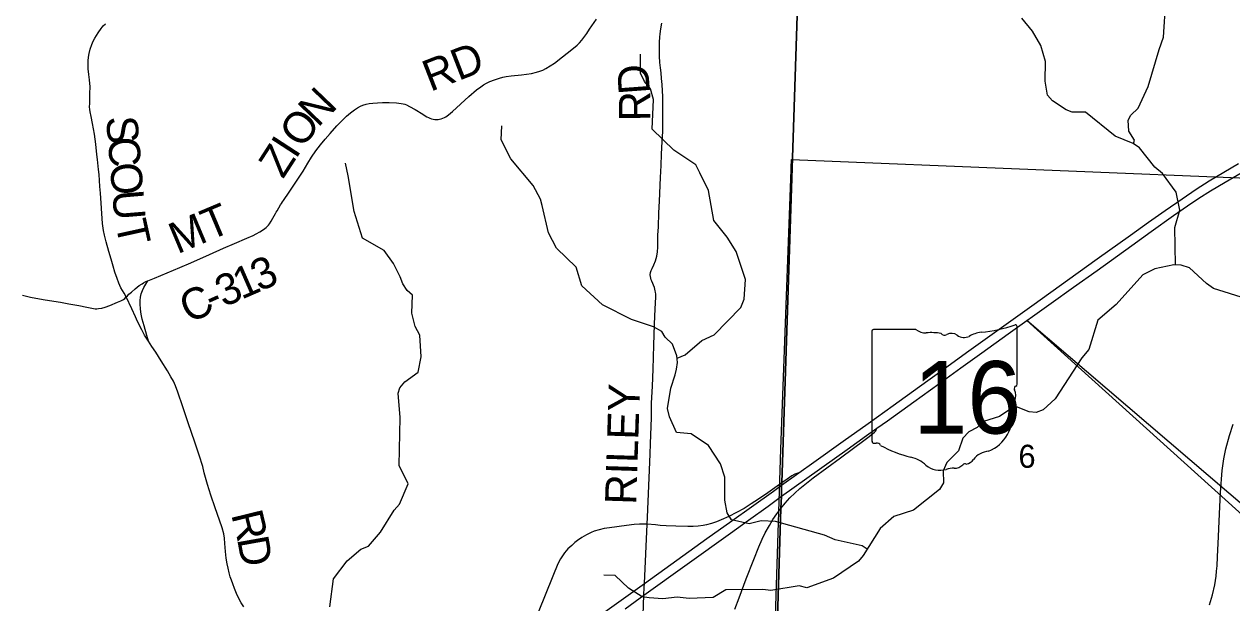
# Model space of a CAD drawing. Extents: x 0 to 34, y 0 to 22.
# Drawn here: x 4.796 to 6.991, y 19.468 to 20.52 of the extents above; entities that cross this region are included whole.
import ezdxf

# ---------------------------------------------------------------- set-up
doc = ezdxf.new("R2010")
doc.units = 0
for name, color, linetype in [('GM_X_County_Road', 7, 'Continuous'), ('GM_X_County_Road_Text', 7, 'Continuous'), ('GM_X_Interchange_Ramps', 7, 'Continuous'), ('GM_X_Minor_River', 7, 'Continuous'), ('GM_X_Section', 7, 'Continuous'), ('GM_X_Section_Text', 7, 'Continuous'), ('GM_X_State_Location', 7, 'Continuous'), ('GM_X_State_Route', 7, 'Continuous'), ('GM_X_State_Shield', 7, 'Continuous'), ('GM_X_Township', 7, 'Continuous'), ('GM_X_Township_Road', 7, 'Continuous'), ('GM_X_Township_Road_Text', 7, 'Continuous'), ('SH_Data', 7, 'Continuous')]:
    doc.layers.add(name, color=color, linetype=linetype)

msp = doc.modelspace()

# ---------------------------------------------------------------- linework, layer by layer
at = {"layer": 'GM_X_County_Road'}
for points in [[(5.021, 20.0533), (5.0333, 20.0583), (5.0791, 20.0773), (5.099, 20.086), (5.1329, 20.1014), (5.1585, 20.1128), (5.1785, 20.1211), (5.2011, 20.1308), (5.2125, 20.1358), (5.218, 20.1386), (5.2249, 20.1423), (5.2313, 20.1466), (5.2359, 20.1502), (5.2382, 20.1522), (5.2402, 20.1544), (5.2421, 20.1568), (5.2453, 20.162), (5.2484, 20.1673), (5.2529, 20.1754), (5.2545, 20.1781), (5.256, 20.1808), (5.2591, 20.1862), (5.2624, 20.1915), (5.2641, 20.194), (5.2658, 20.1966), (5.2676, 20.1991), (5.2781, 20.2145), (5.2915, 20.2344), (5.3031, 20.2528), (5.312, 20.2673), (5.3187, 20.2778), (5.3265, 20.2897), (5.3347, 20.3006), (5.3433, 20.3111), (5.3522, 20.3214), (5.3647, 20.335), (5.3753, 20.3461), (5.3821, 20.3526), (5.3892, 20.3587), (5.3967, 20.3644), (5.4019, 20.3679), (5.4077, 20.3706), (5.4118, 20.3724), (5.4176, 20.3744), (5.4231, 20.3756), (5.4299, 20.3763), (5.4382, 20.3769), (5.4476, 20.3772), (5.4595, 20.3772), (5.4731, 20.3768), (5.4818, 20.3757), (5.4849, 20.375), (5.488, 20.3742), (5.491, 20.3731), (5.4966, 20.3703), (5.5072, 20.3645), (5.5098, 20.363), (5.5177, 20.358), (5.5283, 20.3516), (5.531, 20.3502), (5.5338, 20.3489), (5.5367, 20.3479), (5.5396, 20.3471), (5.5425, 20.3465), (5.5455, 20.3464), (5.5485, 20.3465), (5.5514, 20.347), (5.5544, 20.3477), (5.5572, 20.3487), (5.56, 20.35), (5.5626, 20.3515), (5.5676, 20.355), (5.5747, 20.3609), (5.6046, 20.3881), (5.6187, 20.4003), (5.6261, 20.406), (5.6313, 20.4096), (5.6368, 20.4127), (5.6424, 20.4154), (5.6511, 20.4189), (5.66, 20.4218), (5.6661, 20.4234), (5.6723, 20.4245), (5.6815, 20.4258), (5.7001, 20.4276), (5.7093, 20.4287), (5.7185, 20.4302), (5.7275, 20.4324), (5.7333, 20.4342), (5.7391, 20.4365), (5.7446, 20.4392), (5.7525, 20.4439), (5.7601, 20.4492), (5.7748, 20.4605), (5.7919, 20.474), (5.8014, 20.4819), (5.8059, 20.4861), (5.8101, 20.4906), (5.8138, 20.4954), (5.8189, 20.5032), (5.8239, 20.511), (5.8367, 20.5287)], [(4.9817, 20.0239), (4.9778, 20.0308), (4.9722, 20.0407), (4.9684, 20.049), (4.9651, 20.0573), (4.9613, 20.0688), (4.958, 20.0798), (4.9544, 20.0925), (4.9504, 20.1069), (4.9451, 20.1242), (4.942, 20.1362), (4.9402, 20.145), (4.9387, 20.1573), (4.9373, 20.1758), (4.9361, 20.1944), (4.9349, 20.2129), (4.934, 20.225), (4.9324, 20.2463), (4.9315, 20.2555), (4.9294, 20.274), (4.9284, 20.2832), (4.9265, 20.3017), (4.9242, 20.3202), (4.9206, 20.3396), (4.9181, 20.3518), (4.9164, 20.3604), (4.9156, 20.3648), (4.9153, 20.3697), (4.9156, 20.3756), (4.9156, 20.3838), (4.9159, 20.3941), (4.9162, 20.4061), (4.9151, 20.4185), (4.9136, 20.4286), (4.9125, 20.4386), (4.9125, 20.4479), (4.9128, 20.4535), (4.9134, 20.4599), (4.9147, 20.4663), (4.9164, 20.4743), (4.9192, 20.4828), (4.9217, 20.4892), (4.9245, 20.4947), (4.9275, 20.4994), (4.9309, 20.5042), (4.9363, 20.5118), (4.94, 20.5166), (4.944, 20.5207)], [(4.9817, 20.0239), (4.9839, 20.0263), (4.9863, 20.0289), (4.9912, 20.0326), (4.9982, 20.0386), (5.0054, 20.0445), (5.0105, 20.0481), (5.0132, 20.0497), (5.0172, 20.0518), (5.021, 20.0533)], [(5.0222, 19.9435), (5.0192, 19.954), (5.0141, 19.9716), (5.0109, 19.9836), (5.009, 19.9927), (5.0076, 20.0019), (5.007, 20.0113), (5.0071, 20.0175), (5.0078, 20.0237), (5.0091, 20.0298), (5.01, 20.0328), (5.0111, 20.0357), (5.0138, 20.0413), (5.0154, 20.044), (5.021, 20.0533)], [(5.0222, 19.9435), (5.0152, 19.9545), (5.0099, 19.9642), (5.0025, 19.9796), (4.9985, 19.9881), (4.9919, 20.0024), (4.9817, 20.0239)], [(5.1956, 19.4608), (5.1907, 19.4682), (5.1864, 19.4758), (5.1821, 19.4846), (5.1786, 19.4938), (5.1754, 19.5023), (5.1731, 19.5089), (5.1708, 19.5154), (5.1686, 19.5224), (5.1668, 19.5307), (5.1653, 19.5388), (5.1637, 19.5489), (5.1625, 19.5613), (5.1613, 19.5756), (5.1605, 19.5854), (5.159, 19.5935), (5.1562, 19.6041), (5.1516, 19.618), (5.1437, 19.6406), (5.1358, 19.6634), (5.1294, 19.6833), (5.1237, 19.7045), (5.1209, 19.7156), (5.1145, 19.7364), (5.1067, 19.7599), (5.0946, 19.7951), (5.0846, 19.8244), (5.0756, 19.8507), (5.0712, 19.8623), (5.0674, 19.8708), (5.063, 19.8789), (5.0567, 19.8896), (5.0453, 19.908), (5.0353, 19.9237), (5.0284, 19.934), (5.0222, 19.9435)], [(6.9507, 19.4645), (6.9561, 19.4824), (6.9603, 19.5006), (6.9627, 19.5161), (6.9637, 19.5255), (6.9645, 19.5352), (6.9653, 19.5514), (6.9669, 19.5883), (6.9683, 19.6163), (6.9705, 19.6682), (6.974, 19.7084), (6.9769, 19.7299), (6.9806, 19.7481), (6.9871, 19.7721), (6.9939, 19.7927)]]:
    msp.add_lwpolyline(points, dxfattribs=at)
at = {"layer": 'GM_X_Interchange_Ramps'}
for points in [[(6.0878, 19.4563), (6.0956, 19.4767), (6.1087, 19.5117), (6.1223, 19.5466), (6.1316, 19.5697), (6.1379, 19.5839), (6.1433, 19.5952), (6.1508, 19.6088), (6.1573, 19.6194), (6.1643, 19.6297), (6.1717, 19.6397), (6.1797, 19.6493), (6.188, 19.6585), (6.1968, 19.6673), (6.206, 19.6756), (6.218, 19.6856), (6.2303, 19.6951), (6.2799, 19.7317), (6.3252, 19.7651), (6.3323, 19.7702), (6.3418, 19.7781), (6.344, 19.7807), (6.3464, 19.7852)], [(6.2041, 19.7041), (6.1972, 19.702), (6.1917, 19.699), (6.1829, 19.6926), (6.1733, 19.6859), (6.1479, 19.668), (6.131, 19.6561), (6.118, 19.6476), (6.1047, 19.6395), (6.0911, 19.632), (6.0772, 19.625), (6.0631, 19.6185), (6.0544, 19.615), (6.0456, 19.612), (6.0366, 19.6096), (6.0305, 19.6084), (6.0213, 19.6071), (6.012, 19.6065), (6.0027, 19.6064), (5.981, 19.6073), (5.9629, 19.608), (5.9524, 19.6086), (5.944, 19.6096), (5.9286, 19.6111)], [(5.9286, 19.6111), (5.9193, 19.6112), (5.9148, 19.6111), (5.9053, 19.6103), (5.8909, 19.6086), (5.8599, 19.6044), (5.8506, 19.6028), (5.8414, 19.6007), (5.8324, 19.5979), (5.8266, 19.5956), (5.8181, 19.5915), (5.8099, 19.5867), (5.8022, 19.5813), (5.7974, 19.5774), (5.7915, 19.5724), (5.7846, 19.5658), (5.7783, 19.5589), (5.7709, 19.5482), (5.7662, 19.5391), (5.7574, 19.5166), (5.7176, 19.4189)]]:
    msp.add_lwpolyline(points, dxfattribs=at)
at = {"layer": 'GM_X_Minor_River'}
for points in [[(6.8124, 20.3022), (6.8144, 20.3091), (6.8041, 20.3254), (6.8029, 20.3451), (6.8078, 20.3547), (6.8213, 20.3672), (6.8394, 20.4064), (6.8595, 20.474), (6.8674, 20.4964), (6.8716, 20.5616), (6.8769, 20.5715), (6.9002, 20.594), (6.9175, 20.6195), (6.9194, 20.6316), (6.9151, 20.6547), (6.9132, 20.6673), (6.8853, 20.7275), (6.8693, 20.7532), (6.8317, 20.8506)], [(6.889, 20.0821), (6.8878, 20.1504), (6.8967, 20.1816), (6.8901, 20.2142), (6.8654, 20.2486), (6.8517, 20.26), (6.8236, 20.2948), (6.8118, 20.3027), (6.7796, 20.3162), (6.7256, 20.3597), (6.7014, 20.3596), (6.69, 20.3641), (6.6653, 20.3803), (6.6562, 20.3906), (6.6519, 20.416), (6.6529, 20.452), (6.6445, 20.4808), (6.6288, 20.5073), (6.6094, 20.5308)], [(5.983, 19.9125), (5.9977, 19.9186), (6.0278, 19.9449), (6.0505, 19.9552), (6.0991, 20.0051), (6.1047, 20.0199), (6.1076, 20.0556), (6.0904, 20.1067), (6.0743, 20.1329), (6.05, 20.1631), (6.0403, 20.2173), (6.0246, 20.2495), (6.0174, 20.2643), (5.9771, 20.2911), (5.9376, 20.3289), (5.9404, 20.3828), (5.9346, 20.4025), (5.924, 20.4158), (5.9167, 20.4305), (5.9166, 20.4654)], [(6.3285, 19.5653), (6.3194, 19.5714), (6.2702, 19.5823), (6.2512, 19.5909), (6.1618, 19.6157), (6.1356, 19.6167), (6.1141, 19.6113), (6.0819, 19.6188), (6.0739, 19.6317), (6.07, 19.6548), (6.0698, 19.6965), (6.0621, 19.7208), (6.0404, 19.7541), (6.0085, 19.7752), (5.982, 19.7778), (5.969, 19.8058), (5.9655, 19.8214), (5.9714, 19.8582), (5.9793, 19.8825), (5.9819, 19.8924), (5.9837, 19.9049), (5.9825, 19.9167), (5.9745, 19.9379), (5.9616, 19.9507), (5.9555, 19.9614), (5.9403, 19.9696), (5.9001, 19.9828), (5.8477, 20.0095), (5.8097, 20.0443), (5.7998, 20.0781), (5.764, 20.1125), (5.7495, 20.1405), (5.7379, 20.1905), (5.7349, 20.2019), (5.7215, 20.2265), (5.6808, 20.2749), (5.6632, 20.3094), (5.6643, 20.3352)], [(5.3517, 19.4604), (5.3585, 19.5113), (5.3834, 19.5444), (5.4083, 19.5657), (5.4219, 19.5707), (5.4441, 19.5962), (5.4685, 19.6361), (5.4787, 19.6471), (5.4944, 19.684), (5.4776, 19.7177), (5.4795, 19.8049), (5.4763, 19.8489), (5.4789, 19.8588), (5.488, 19.8698), (5.5125, 19.887), (5.5181, 19.9151), (5.5152, 19.9545), (5.5072, 19.9705), (5.5011, 19.9947), (5.502, 20.0273), (5.4922, 20.0357), (5.4845, 20.0478), (5.4799, 20.0603), (5.4673, 20.0849), (5.4506, 20.1084), (5.4111, 20.131), (5.3958, 20.1791), (5.3849, 20.2443), (5.3806, 20.2671)], [(7.0178, 20.0208), (6.9583, 20.0391), (6.9454, 20.0482), (6.9142, 20.0769), (6.8991, 20.0818), (6.8862, 20.0821), (6.8514, 20.0752), (6.8295, 20.0641), (6.7813, 20.0101), (6.7481, 19.9815), (6.7313, 19.9283), (6.7188, 19.9135), (6.6703, 19.8386), (6.6485, 19.8188), (6.636, 19.8142), (6.6231, 19.8153), (6.5969, 19.8254), (6.569, 19.8064), (6.5399, 19.7975), (6.5286, 19.7869), (6.5135, 19.7789), (6.5022, 19.7671), (6.4947, 19.7443), (6.4736, 19.7233), (6.4665, 19.7078), (6.4673, 19.6861), (6.4602, 19.674), (6.413, 19.6366), (6.3771, 19.6251), (6.3522, 19.603), (6.3214, 19.554), (6.3127, 19.5437), (6.2674, 19.5125), (6.2191, 19.4952), (6.205, 19.499), (6.1532, 19.4904), (6.1388, 19.4923), (6.0718, 19.4917), (6.0488, 19.4776), (6.0049, 19.4755), (5.9833, 19.4785), (5.9572, 19.4754), (5.9322, 19.4768), (5.9197, 19.4786), (5.895, 19.4945), (5.8707, 19.5176), (5.8499, 19.5182)]]:
    msp.add_lwpolyline(points, dxfattribs=at)
at = {"layer": 'GM_X_Section'}
msp.add_lwpolyline([(6.1908, 20.2736), (7.0795, 20.2374), (7.0553, 19.2199), (6.1559, 19.253), (6.1718, 19.7471), (6.1903, 20.2549), (6.1905, 20.2588)], close=True, dxfattribs=at)
at = {"layer": 'GM_X_State_Route'}
for points in [[(5.5782, 19.2562), (5.9237, 19.5033), (5.9716, 19.5375), (6.0372, 19.5846), (6.0827, 19.6171), (6.1181, 19.6423), (6.1585, 19.6712), (6.1731, 19.6818), (6.2041, 19.7041), (6.2316, 19.7239), (6.2847, 19.7617), (6.3302, 19.7942), (6.3757, 19.8266), (6.4237, 19.861), (6.4666, 19.8918), (6.5094, 19.9227), (6.628, 20.0077), (6.7465, 20.093), (6.8072, 20.1362), (6.8399, 20.1598), (6.8703, 20.1814), (6.901, 20.2026), (6.9268, 20.2198), (6.9503, 20.2348), (6.9768, 20.2509), (7.0037, 20.2664)], [(5.8885, 19.4569), (5.9162, 19.4769), (5.9228, 19.4816), (6.0801, 19.5948), (6.1129, 19.6184), (6.1483, 19.6436), (6.1731, 19.6616), (6.1961, 19.6782), (6.2921, 19.7467), (6.3275, 19.7719), (6.3464, 19.7852), (6.3656, 19.7988), (6.4134, 19.8333), (6.4587, 19.8661), (6.4991, 19.895), (6.537, 19.9222), (6.5848, 19.9567), (6.6632, 20.0126), (6.7035, 20.0417), (6.7465, 20.0722), (6.8095, 20.1176), (6.8449, 20.1429), (6.8854, 20.1718), (6.9108, 20.1896), (6.9314, 20.2035), (6.9524, 20.2168), (6.979, 20.2329), (7.0086, 20.2499)]]:
    msp.add_lwpolyline(points, dxfattribs=at)
at = {"layer": 'GM_X_State_Shield'}
for p, q in [((6.3373, 19.9616), (6.3373, 19.7615)), ((6.4171, 19.9651), (6.3399, 19.9651)), ((6.601, 19.8653), (6.601, 19.97)), ((6.601, 19.8654), (6.601, 19.8653))]:
    msp.add_line(p, q, dxfattribs=at)
for centre, radius, start, end in [((6.3403, 19.962), 0.00305, 98.1301, 188.1301), ((6.4355, 19.9883), 0.0296, 231.6195, 271.1119), ((6.4453, 19.8527), 0.1064, 80.4867, 94.9883), ((6.4695, 19.9631), 0.00855, 219.7921, 297.1024), ((6.482, 19.94), 0.0178, 54.4667, 119.1411), ((6.505, 19.9717), 0.0214, 233.8562, 294.8282), ((6.5427, 19.9039), 0.0563, 97.3462, 120.7689), ((6.5071, 20.2379), 0.2796, 275.8445, 288.9065), ((6.5981, 19.9705), 0.00294, 351.8621, 97.738), ((6.6003, 19.8576), 0.00454, 107.944, 210.337), ((6.5714, 19.8444), 0.0273, 340.033, 23.6496), ((6.5979, 19.8649), 0.00314, 289.6038, 7.7341), ((6.6115, 19.8215), 0.0198, 136.8065, 186.9296), ((6.5227, 19.8082), 0.0699, 292.3089, 8.9858), ((6.3404, 19.7611), 0.00308, 171.9584, 258.3066), ((6.3408, 19.7815), 0.0235, 267.339, 280.6039), ((6.3456, 19.75), 0.00848, 29.7484, 93.2717), ((6.4527, 19.9298), 0.2019, 240.4129, 257.1985), ((6.5522, 19.7053), 0.0383, 94.4031, 142.5768), ((6.3925, 19.6716), 0.0632, 47.1842, 75.836), ((6.4608, 19.749), 0.0401, 230.7004, 286.2918), ((6.484, 19.6798), 0.0329, 85.6951, 111.2099), ((6.4869, 19.734), 0.0214, 268.777, 315.5493), ((6.5063, 19.7146), 0.00601, 65.7517, 132.6484), ((6.5037, 19.7421), 0.0226, 282.8732, 323.2771)]:
    msp.add_arc(centre, radius, start, end, dxfattribs=at)
at = {"layer": 'GM_X_Township'}
for points in [[(2.6013, 16.5379), (2.8688, 16.5234), (3.5006, 16.5009), (4.2928, 16.4705), (5.2983, 16.434), (6.0664, 16.4042), (6.0778, 16.7443), (6.0911, 17.2548), (6.11, 17.7459), (6.1473, 18.845), (6.1717, 19.6397), (6.1731, 19.6616), (6.1731, 19.6818), (6.1733, 19.6859), (6.2234, 21.2003)], [(6.2234, 21.2003), (6.1733, 19.6859), (6.1731, 19.6818), (6.1731, 19.6616), (6.1717, 19.6397), (6.1473, 18.845), (6.11, 17.7459), (6.0911, 17.2548), (6.0778, 16.7443), (6.0664, 16.4042), (6.0598, 16.2379), (6.2085, 16.2337), (6.3056, 16.228), (6.5048, 16.2253), (7.5772, 16.1862), (7.7357, 16.1804), (8.4842, 16.1527), (8.5405, 16.1503), (9.1818, 16.131), (9.4013, 16.1226)]]:
    msp.add_lwpolyline(points, dxfattribs=at)
at = {"layer": 'GM_X_Township_Road'}
for points in [[(5.9365, 19.8142), (5.9368, 19.8308), (5.9381, 19.8618), (5.9394, 19.8929), (5.9409, 19.9363), (5.9419, 19.9736), (5.9425, 19.9891), (5.9439, 20.0138), (5.9443, 20.0231), (5.9442, 20.0293), (5.944, 20.0324), (5.9435, 20.0354), (5.942, 20.0413), (5.9371, 20.0525), (5.936, 20.0554), (5.9352, 20.0583), (5.9346, 20.0613), (5.9343, 20.0643), (5.9347, 20.0684), (5.9357, 20.072), (5.9375, 20.0756), (5.9406, 20.0824), (5.944, 20.0899), (5.9462, 20.0983), (5.9472, 20.1059), (5.9478, 20.1144), (5.9482, 20.1366), (5.9491, 20.1517), (5.95, 20.1769), (5.9513, 20.1979), (5.9531, 20.2413), (5.9541, 20.263), (5.9549, 20.2833), (5.956, 20.3063), (5.9571, 20.3249), (5.957, 20.3876), (5.9558, 20.4101), (5.9548, 20.4214), (5.9539, 20.4316), (5.9527, 20.4405), (5.9517, 20.4503), (5.9512, 20.4616), (5.9512, 20.481), (5.9513, 20.4871), (5.9519, 20.4963), (5.9525, 20.5024), (5.9536, 20.5114), (5.9551, 20.5219)], [(4.793, 20.0272), (4.8079, 20.0236), (4.8307, 20.0196), (4.85, 20.0165), (4.8622, 20.0143), (4.8774, 20.0116), (4.8954, 20.0082), (4.9104, 20.0052), (4.9194, 20.0034), (4.9255, 20.0026), (4.9285, 20.0025), (4.9315, 20.0027), (4.9374, 20.0037), (4.9433, 20.0053), (4.9519, 20.0087), (4.9658, 20.0147), (4.9717, 20.0171), (4.9771, 20.0193), (4.9793, 20.0209), (4.9817, 20.0239)], [(5.9286, 19.6111), (5.9293, 19.6239), (5.9333, 19.7235), (5.934, 19.7387), (5.9348, 19.7567), (5.9363, 19.8047), (5.9365, 19.8142)], [(5.9184, 19.3696), (5.92, 19.4096), (5.9228, 19.4816), (5.9233, 19.4961), (5.9237, 19.5033), (5.9286, 19.6111)]]:
    msp.add_lwpolyline(points, dxfattribs=at)
at = {"layer": 'SH_Data'}
msp.add_lwpolyline([(6.619, 19.9811), (10.5909, 16.3957), (10.5909, 16.5853)], close=True, dxfattribs=at)

# ---------------------------------------------------------------- texts
at = {"layer": 'GM_X_County_Road_Text'}
for s, height, rotation, p in [('RD', 0.05682, 21.2508, (5.5346, 20.3967)), ('N', 0.0568, 46.1721, (5.3303, 20.3308)), ('O', 0.0568, 53.8885, (5.3021, 20.292)), ('S', 0.0568, 274.7475, (4.9449, 20.3508)), ('C', 0.0568, 274.7474, (4.9481, 20.3126)), ('I', 0.0568, 56.9768, (5.2899, 20.2731)), ('Z', 0.0568, 57.1551, (5.2668, 20.2374)), ('O', 0.0568, 274.7491, (4.9519, 20.2661)), ('U', 0.0568, 274.8228, (4.9561, 20.2162)), ('MT', 0.05682, 22.7872, (5.0748, 20.1014)), ('T', 0.0568, 282.4088, (4.9615, 20.1582)), ('3', 0.0568, 24.2253, (5.2239, 20.033)), ('3', 0.0568, 23.6359, (5.1592, 20.0047)), ('1', 0.0568, 23.6243, (5.1912, 20.0187)), ('C', 0.0568, 26.504, (5.0968, 19.9747)), ('-', 0.0568, 24.0647, (5.138, 19.9952)), ('R', 0.0568, 283.8138, (5.1723, 19.6287)), ('D', 0.0568, 280.1361, (5.1832, 19.5843))]:
    msp.add_text(s, height=height, rotation=rotation, dxfattribs=at).set_placement(p)
at = {"layer": 'GM_X_Section_Text'}
msp.add_text('6', height=0.0419, rotation=0, dxfattribs=at).set_placement((6.6035, 19.7134))
at = {"layer": 'GM_X_State_Location'}
for s in ['s', 'r']:
    msp.add_text(s, height=0.000189, dxfattribs=at).set_placement((6.4662, 19.8483))
msp.add_text('16', height=0.000189, rotation=0, dxfattribs=at).set_placement((6.4185, 19.8345))
at = {"layer": 'GM_X_State_Shield'}
msp.add_text('16', height=0.13184, dxfattribs=at).set_placement((6.4125, 19.7756))
at = {"layer": 'GM_X_Township_Road_Text'}
for s, height, rotation, p in [('D', 0.0568, 94.2008, (5.934, 20.3942)), ('R', 0.0568, 90.4059, (5.9345, 20.3435)), ('RILEY', 0.05682, 88.1441, (5.9087, 19.6457))]:
    msp.add_text(s, height=height, rotation=rotation, dxfattribs=at).set_placement(p)

doc.saveas('drawing.dxf')
